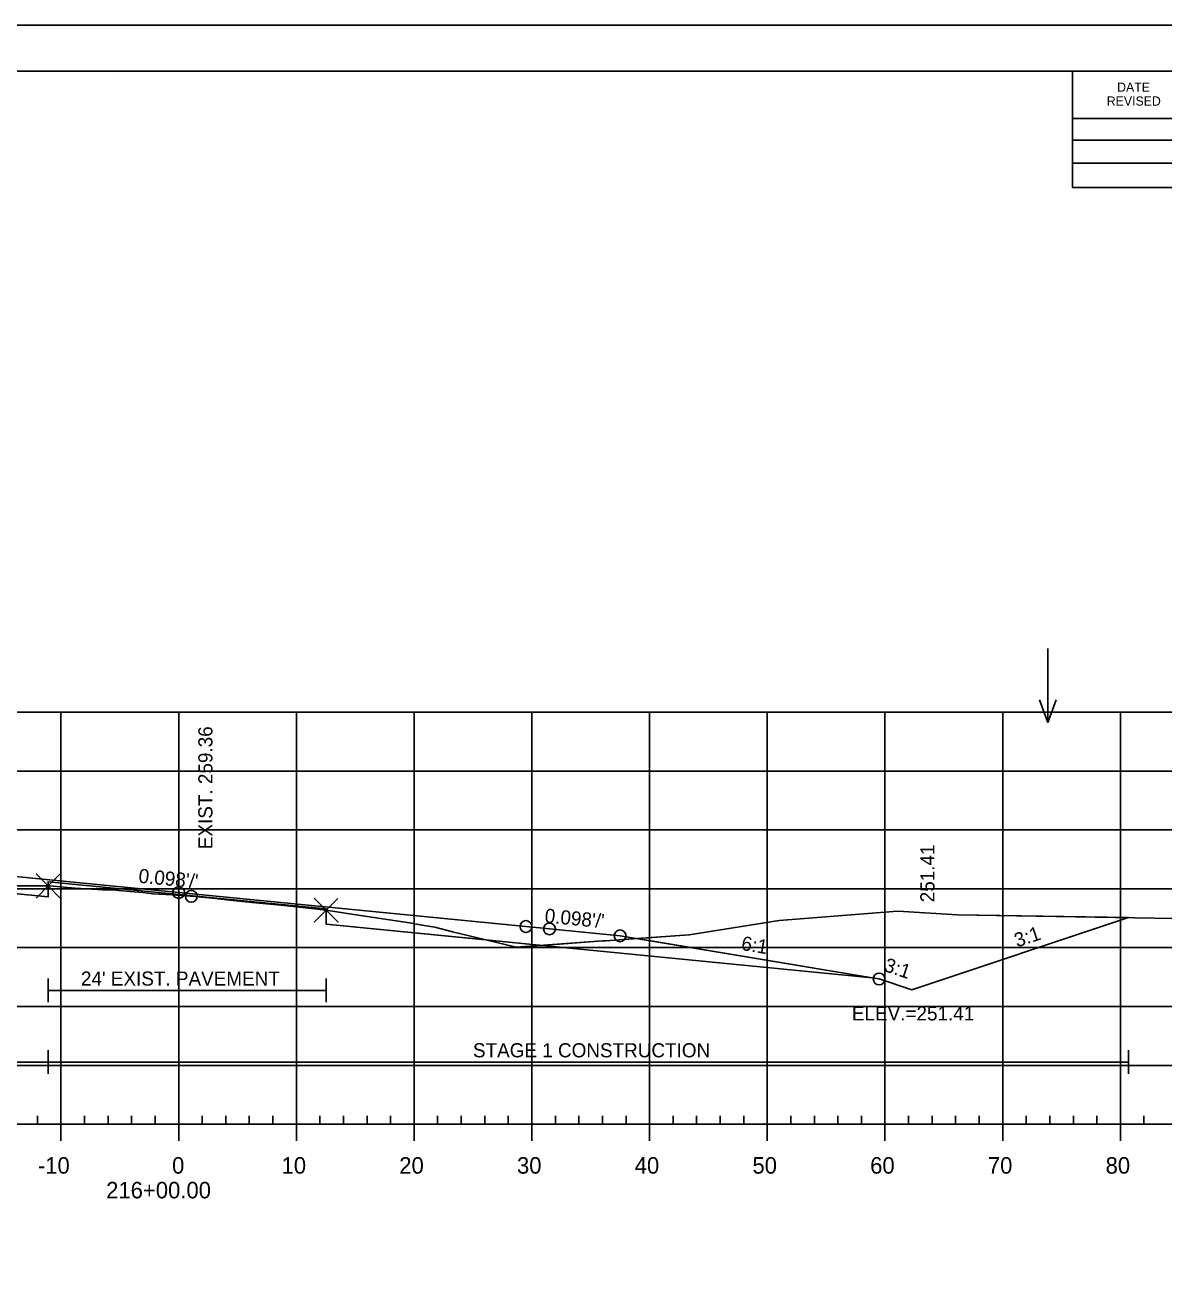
# Model space of a CAD drawing. Extents: x 1365647 to 1367999, y 387113 to 400173.
# Drawn here: x 1365881 to 1365977.8, y 390892.8 to 390999.5 of the extents above; entities that cross this region are included whole.
import ezdxf

# ---------------------------------------------------------------- set-up
doc = ezdxf.new("R2010")
doc.units = 0
for name, color, linetype in [('R_Alt Surface', 7, 'Continuous'), ('R_Axis', 7, 'Continuous'), ('R_Axis Annot', 7, 'Continuous'), ('R_Border', 7, 'Continuous'), ('R_Border Notes', 7, 'Continuous'), ('R_Contours', 7, 'Continuous'), ('R_Exist Surface', 7, 'Continuous'), ('R_Fin Surface', 7, 'Continuous'), ('R_Fin Surface Annot', 7, 'Continuous'), ('R_Grid', 7, 'Continuous'), ('R_No Plot', 7, 'Continuous'), ('R_Water', 7, 'Continuous'), ('R_Water Annot', 7, 'Continuous'), ('R_Xsect Elev', 7, 'Continuous')]:
    doc.layers.add(name, color=color, linetype=linetype)

msp = doc.modelspace()

# ---------------------------------------------------------------- linework, layer by layer
at = {"layer": 'R_Alt Surface'}
msp.add_lwpolyline([(1365834.58, 390928.1), (1365834.58, 390926.86), (1365862.58, 390927.42), (1365882.99, 390925.43), (1365882.99, 390926.72), (1365894.08, 390925.63), (1365906.61, 390924.4), (1365906.61, 390923.11), (1365925.58, 390921.25), (1365953, 390918.55)], dxfattribs=at)
at = {"layer": 'R_Axis'}
for p, q in [((1365749.08, 390906.12), (1366039.08, 390906.12)), ((1365882.08, 390906.12), (1365882.08, 390906.82)), ((1365884.08, 390904.72), (1365884.08, 390906.12)), ((1365886.08, 390906.12), (1365886.08, 390906.82)), ((1365888.08, 390906.12), (1365888.08, 390906.82)), ((1365890.08, 390906.12), (1365890.08, 390906.82)), ((1365892.08, 390906.12), (1365892.08, 390906.82)), ((1365894.08, 390904.72), (1365894.08, 390906.12)), ((1365896.08, 390906.12), (1365896.08, 390906.82)), ((1365898.08, 390906.12), (1365898.08, 390906.82)), ((1365900.08, 390906.12), (1365900.08, 390906.82)), ((1365902.08, 390906.12), (1365902.08, 390906.82)), ((1365904.08, 390904.72), (1365904.08, 390906.12)), ((1365906.08, 390906.12), (1365906.08, 390906.82)), ((1365908.08, 390906.12), (1365908.08, 390906.82)), ((1365910.08, 390906.12), (1365910.08, 390906.82)), ((1365912.08, 390906.12), (1365912.08, 390906.82)), ((1365914.08, 390904.72), (1365914.08, 390906.12)), ((1365916.08, 390906.12), (1365916.08, 390906.82)), ((1365918.08, 390906.12), (1365918.08, 390906.82)), ((1365920.08, 390906.12), (1365920.08, 390906.82)), ((1365922.08, 390906.12), (1365922.08, 390906.82)), ((1365924.08, 390904.72), (1365924.08, 390906.12)), ((1365926.08, 390906.12), (1365926.08, 390906.82)), ((1365928.08, 390906.12), (1365928.08, 390906.82)), ((1365930.08, 390906.12), (1365930.08, 390906.82)), ((1365932.08, 390906.12), (1365932.08, 390906.82)), ((1365934.08, 390904.72), (1365934.08, 390906.12)), ((1365936.08, 390906.12), (1365936.08, 390906.82)), ((1365938.08, 390906.12), (1365938.08, 390906.82)), ((1365940.08, 390906.12), (1365940.08, 390906.82)), ((1365942.08, 390906.12), (1365942.08, 390906.82)), ((1365944.08, 390904.72), (1365944.08, 390906.12)), ((1365946.08, 390906.12), (1365946.08, 390906.82)), ((1365948.08, 390906.12), (1365948.08, 390906.82)), ((1365950.08, 390906.12), (1365950.08, 390906.82)), ((1365952.08, 390906.12), (1365952.08, 390906.82)), ((1365954.08, 390904.72), (1365954.08, 390906.12)), ((1365956.08, 390906.12), (1365956.08, 390906.82)), ((1365958.08, 390906.12), (1365958.08, 390906.82)), ((1365960.08, 390906.12), (1365960.08, 390906.82)), ((1365962.08, 390906.12), (1365962.08, 390906.82)), ((1365964.08, 390904.72), (1365964.08, 390906.12)), ((1365966.08, 390906.12), (1365966.08, 390906.82)), ((1365968.08, 390906.12), (1365968.08, 390906.82)), ((1365970.08, 390906.12), (1365970.08, 390906.82)), ((1365972.08, 390906.12), (1365972.08, 390906.82)), ((1365974.08, 390904.72), (1365974.08, 390906.12)), ((1365976.08, 390906.12), (1365976.08, 390906.82))]:
    msp.add_line(p, q, dxfattribs=at)
at = {"layer": 'R_Border'}
for p, q in [((1365736.08, 390995.58), (1366052.26, 390995.58)), ((1365970, 390985.7), (1365970, 390995.58)), ((1365888.6, 390995.32), (1365888.6, 390995.32)), ((1365888.6, 390995.32), (1365888.6, 390995.32)), ((1365970, 390991.56), (1366009.16, 390991.56)), ((1365970, 390989.7), (1366009.16, 390989.7)), ((1365970, 390985.7), (1365970, 390987.76)), ((1365970, 390987.76), (1366009.16, 390987.76)), ((1366052.26, 390985.7), (1365970, 390985.7))]:
    msp.add_line(p, q, dxfattribs=at)
at = {"layer": 'R_Contours'}
for p, q in [((1365906.61, 390924.3), (1365906.61, 390923.11)), ((1365906.61, 390923.11), (1365920.18, 390921.78)), ((1365924.95, 390921.31), (1365925.58, 390921.25)), ((1365925.58, 390921.25), (1365953, 390918.55)), ((1365933, 390921.89), (1365953, 390918.55)), ((1365953, 390918.55), (1365933, 390921.89))]:
    msp.add_line(p, q, dxfattribs=at)
for points in [[(1365873.17, 390926.39), (1365877.46, 390926.37), (1365877.71, 390926.37), (1365881.64, 390926.38), (1365882.99, 390926.36), (1365882.99, 390925.43)], [(1365882.99, 390926.36), (1365883.42, 390926.33), (1365884.33, 390926.26), (1365885.29, 390926.17), (1365886.26, 390926.11), (1365887.65, 390926.03), (1365888.4, 390926.03), (1365889.32, 390925.95), (1365890.29, 390925.86), (1365891.03, 390925.79), (1365891.89, 390925.7), (1365893.53, 390925.6), (1365895.04, 390925.49), (1365895.15, 390925.48), (1365895.45, 390925.46), (1365896.31, 390925.38), (1365896.96, 390925.33), (1365898.43, 390925.15), (1365899.51, 390925.03), (1365900.6, 390924.93), (1365902.79, 390924.73), (1365905.37, 390924.44), (1365906.61, 390924.3), (1365906.61, 390924.4), (1365894.08, 390925.63), (1365882.99, 390926.72)], [(1365906.61, 390924.3), (1365908.96, 390923.94), (1365913.7, 390923.23), (1365914.76, 390923.02), (1365915.83, 390922.85), (1365917.35, 390922.47), (1365920.18, 390921.78), (1365906.61, 390923.11)], [(1365924.95, 390921.31), (1365930.07, 390921.69), (1365930.21, 390921.7), (1365930.36, 390921.7), (1365937.45, 390922.2), (1365937.98, 390922.29), (1365945.08, 390923.41), (1365954.06, 390924.13), (1365955.13, 390924.21), (1365955.66, 390924.18), (1365960.22, 390923.91), (1365974.77, 390923.67), (1365956.36, 390917.53), (1365953.58, 390918.46), (1365953, 390918.55), (1365925.58, 390921.25)], [(1365920.18, 390921.78), (1365922.75, 390921.15), (1365924.95, 390921.31)]]:
    msp.add_lwpolyline(points, close=True, dxfattribs=at)
for points in [[(1365920.18, 390921.78), (1365917.35, 390922.47), (1365915.83, 390922.85), (1365914.76, 390923.02), (1365913.7, 390923.23), (1365908.96, 390923.94), (1365906.61, 390924.3)], [(1365974.77, 390923.67), (1365960.22, 390923.91), (1365955.66, 390924.18), (1365955.13, 390924.21), (1365954.06, 390924.13), (1365945.08, 390923.41), (1365937.98, 390922.29), (1365937.45, 390922.2), (1365933, 390921.89)], [(1365953, 390918.55), (1365953.58, 390918.46), (1365956.36, 390917.53), (1365974.77, 390923.67)], [(1365933, 390921.89), (1365930.36, 390921.7), (1365930.21, 390921.7), (1365930.07, 390921.69), (1365924.95, 390921.31)]]:
    msp.add_lwpolyline(points, dxfattribs=at)
at = {"layer": 'R_Exist Surface'}
msp.add_lwpolyline([(1365877.71, 390926.37), (1365881.64, 390926.38), (1365882.99, 390926.36), (1365883.42, 390926.33), (1365884.33, 390926.26), (1365885.29, 390926.17), (1365886.26, 390926.11), (1365887.65, 390926.03), (1365888.4, 390926.03), (1365889.32, 390925.95), (1365890.29, 390925.86), (1365891.03, 390925.79), (1365891.89, 390925.7), (1365893.53, 390925.6), (1365895.04, 390925.49), (1365895.15, 390925.48), (1365895.45, 390925.46), (1365896.31, 390925.38), (1365896.96, 390925.33), (1365898.43, 390925.15), (1365899.51, 390925.03), (1365900.6, 390924.93), (1365902.79, 390924.73), (1365905.37, 390924.44), (1365906.61, 390924.3), (1365908.96, 390923.94), (1365913.7, 390923.23), (1365914.76, 390923.02), (1365915.83, 390922.85), (1365917.35, 390922.47), (1365922.75, 390921.15), (1365930.07, 390921.69), (1365930.21, 390921.7), (1365930.36, 390921.7), (1365937.45, 390922.2), (1365937.98, 390922.29), (1365945.08, 390923.41), (1365954.06, 390924.13), (1365955.13, 390924.21), (1365955.66, 390924.18), (1365960.22, 390923.91), (1365985.36, 390923.49)], dxfattribs=at)
at = {"layer": 'R_Fin Surface'}
for points in [[(1365834.58, 390928.1), (1365856.58, 390929.47), (1365862.58, 390928.89), (1365864.58, 390928.69), (1365894.08, 390925.8), (1365923.58, 390922.91), (1365925.58, 390922.71), (1365931.58, 390922.12), (1365953, 390918.55), (1365953.58, 390918.46), (1365956.36, 390917.53), (1365974.77, 390923.67)], [(1365856.58, 390929.47), (1365862.58, 390928.89), (1365864.58, 390928.69), (1365894.08, 390925.8), (1365923.58, 390922.91), (1365925.58, 390922.71), (1365931.58, 390922.12)]]:
    msp.add_lwpolyline(points, dxfattribs=at)
at = {"layer": 'R_Grid'}
for p, q in [((1365749.08, 390941.12), (1366039.08, 390941.12)), ((1365884.08, 390906.12), (1365884.08, 390941.12)), ((1365894.08, 390906.12), (1365894.08, 390941.12)), ((1365904.08, 390906.12), (1365904.08, 390941.12)), ((1365914.08, 390906.12), (1365914.08, 390941.12)), ((1365924.08, 390906.12), (1365924.08, 390941.12)), ((1365934.08, 390906.12), (1365934.08, 390941.12)), ((1365944.08, 390906.12), (1365944.08, 390941.12)), ((1365954.08, 390906.12), (1365954.08, 390941.12)), ((1365964.08, 390906.12), (1365964.08, 390941.12)), ((1365974.08, 390906.12), (1365974.08, 390941.12)), ((1365749.08, 390936.12), (1366039.08, 390936.12)), ((1365749.08, 390931.12), (1366039.08, 390931.12)), ((1365749.08, 390926.12), (1366039.08, 390926.12)), ((1365749.08, 390921.12), (1366039.08, 390921.12)), ((1365749.08, 390916.12), (1366039.08, 390916.12)), ((1365749.08, 390911.12), (1366039.08, 390911.12)), ((1365749.08, 390906.12), (1366039.08, 390906.12))]:
    msp.add_line(p, q, dxfattribs=at)
at = {"layer": 'R_No Plot'}
msp.add_line((1365723.68, 390999.48), (1366057.01, 390999.48), dxfattribs=at)
msp.add_lwpolyline([(1365723.67, 390999.48), (1366057.01, 390999.48), (1366057.01, 390786.14), (1365723.67, 390786.14)], close=True, dxfattribs=at)
for points in [[(1365882.99, 390926.36), (1365881.99, 390927.36), (1365882.99, 390926.36), (1365881.99, 390925.36), (1365882.99, 390926.36), (1365883.99, 390925.36), (1365882.99, 390926.36), (1365883.99, 390927.36)], [(1365906.61, 390924.3), (1365905.61, 390925.3), (1365906.61, 390924.3), (1365905.61, 390923.3), (1365906.61, 390924.3), (1365907.61, 390923.3), (1365906.61, 390924.3), (1365907.61, 390925.3)]]:
    msp.add_lwpolyline(points, dxfattribs=at)
for centre in [(1365894.08, 390925.8), (1365894.08, 390925.8), (1365894.08, 390925.8), (1365894.08, 390925.8), (1365894.08, 390925.8), (1365895.15, 390925.48), (1365923.58, 390922.91), (1365923.58, 390922.91), (1365923.58, 390922.91), (1365923.58, 390922.91), (1365923.58, 390922.91), (1365925.58, 390922.71), (1365925.58, 390922.71), (1365925.58, 390922.71), (1365925.58, 390922.71), (1365925.58, 390922.71), (1365931.58, 390922.12), (1365931.58, 390922.12), (1365931.58, 390922.12), (1365931.58, 390922.12), (1365931.58, 390922.12), (1365953.58, 390918.46), (1365953.58, 390918.46), (1365953.58, 390918.46), (1365953.58, 390918.46), (1365953.58, 390918.46)]:
    msp.add_circle(centre, 0.5, dxfattribs=at)
at = {"layer": 'R_Water'}
for p, q in [((1365882.99, 390916.49), (1365882.99, 390918.49)), ((1365906.61, 390916.49), (1365906.61, 390918.49)), ((1365882.99, 390917.49), (1365906.61, 390917.49)), ((1365882.99, 390910.4), (1365882.99, 390912.4)), ((1365974.77, 390910.4), (1365974.77, 390912.4)), ((1365834.58, 390911.4), (1365882.99, 390911.4)), ((1365882.99, 390911.4), (1365974.77, 390911.4))]:
    msp.add_line(p, q, dxfattribs=at)
at = {"layer": 'R_Water Annot'}
for p, q in [((1365967.91, 390946.54), (1365967.91, 390940.25)), ((1365967.91, 390940.25), (1365967.21, 390942.17)), ((1365967.91, 390940.25), (1365968.61, 390942.17))]:
    msp.add_line(p, q, dxfattribs=at)

# ---------------------------------------------------------------- texts
at = {"layer": 'R_Axis Annot'}
for s, p in [('-10', (1365882.12, 390901.92)), ('0', (1365893.52, 390901.92)), ('10', (1365902.82, 390901.92)), ('20', (1365912.82, 390901.92)), ('30', (1365922.82, 390901.92)), ('40', (1365932.82, 390901.92)), ('50', (1365942.82, 390901.92)), ('60', (1365952.82, 390901.92)), ('70', (1365962.82, 390901.92)), ('80', (1365972.82, 390901.92)), ('216+00.00', (1365887.92, 390899.82))]:
    msp.add_text(s, height=1.4, dxfattribs=at).set_placement(p)
at = {"layer": 'R_Border'}
for s, p in [('DATE', (1365973.8, 390993.82)), ('REVISED', (1365972.92, 390992.64))]:
    msp.add_text(s, height=0.782, rotation=360, dxfattribs=at).set_placement(p)
at = {"layer": 'R_Border Notes'}
msp.add_text('ELEV.=251.41', height=1.2, dxfattribs=at).set_placement((1365951.27, 390914.93))
at = {"layer": 'R_Fin Surface Annot'}
for s, rotation, p in [('251.41', 90, (1365958.28, 390924.97)), ("0.098'/'", 354.4029, (1365890.63, 390926.64)), ("0.098'/'", 354.4029, (1365925.13, 390923.26)), ('6:1', 350.5377, (1365941.81, 390920.93)), ('3:1', 18.4349, (1365965.3, 390921.13)), ('3:1', 341.5651, (1365953.91, 390919.15))]:
    msp.add_text(s, height=1.2, rotation=rotation, dxfattribs=at).set_placement(p)
at = {"layer": 'R_Water'}
for s, p in [("24' EXIST. PAVEMENT", (1365885.78, 390917.89)), ('STAGE 1 CONSTRUCTION', (1365919.08, 390911.8))]:
    msp.add_text(s, height=1.2, dxfattribs=at).set_placement(p)
at = {"layer": 'R_Xsect Elev'}
msp.add_text('EXIST. 259.36', height=1.2, rotation=90, dxfattribs=at).set_placement((1365896.95, 390929.48))

doc.saveas('drawing.dxf')
